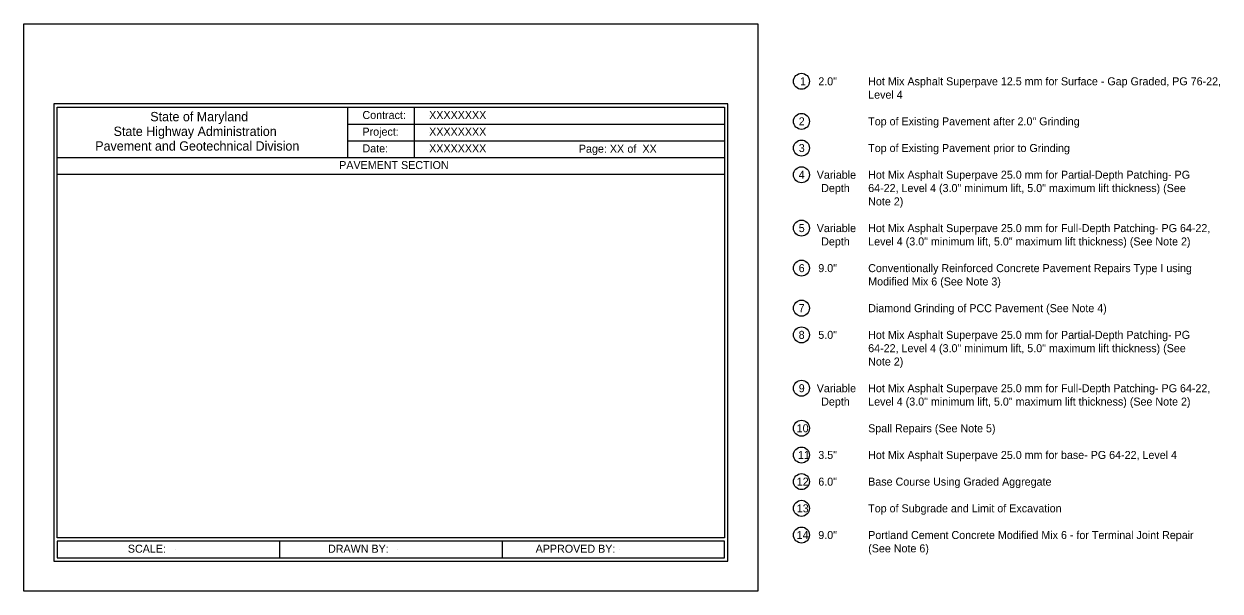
# Model space of a CAD drawing. Extents: x 0 to 17.9, y 0 to 8.5.
import ezdxf

# ---------------------------------------------------------------- set-up
doc = ezdxf.new("R2010")
doc.units = 0
for name, color, linetype in [('BORD-LINE', 7, 'Continuous'), ('BORD-TEXT', 7, 'Continuous'), ('DETL-LABL', 7, 'Continuous'), ('TTLB-TEXT', 7, 'Continuous'), ('USER-PAGE', 7, 'Continuous')]:
    doc.layers.add(name, color=color, linetype=linetype)

msp = doc.modelspace()

# ---------------------------------------------------------------- linework, layer by layer
at = {"layer": 'BORD-LINE'}
for p, q in [((4.85, 7.25), (4.85, 6.5)), ((5.85, 7.25), (5.85, 6.5)), ((4.85, 7), (10.5, 7)), ((6.075, 7.125), (6.075, 7.125)), ((6.075, 6.875), (6.075, 6.875)), ((4.85, 6.75), (10.5, 6.75)), ((0.5, 6.5), (10.5, 6.5)), ((6.075, 6.625), (6.075, 6.625)), ((8.883, 6.62), (8.883, 6.62)), ((9.372, 6.62), (9.372, 6.62)), ((0.5, 6.25), (10.5, 6.25)), ((3.833, 0.75), (3.833, 0.5)), ((7.167, 0.75), (7.167, 0.5)), ((2.267, 0.625), (2.267, 0.625)), ((5.6, 0.625), (5.6, 0.625)), ((8.933, 0.625), (8.933, 0.625)), ((0.5, 0.5), (10.5, 0.5))]:
    msp.add_line(p, q, dxfattribs=at)
for points in [[(0.45, 7.3), (0.45, 0.45), (10.55, 0.45), (10.55, 7.3)], [(0.5, 0.8), (0.5, 7.25), (10.5, 7.25), (10.5, 0.8)], [(0.5, 0.5), (10.5, 0.5), (10.5, 0.75), (0.5, 0.75)]]:
    msp.add_lwpolyline(points, close=True, dxfattribs=at)
at = {"layer": 'DETL-LABL'}
for centre in [(11.656, 7.64), (11.656, 7.04), (11.656, 6.64), (11.656, 6.24), (11.656, 5.44), (11.656, 4.84), (11.656, 4.24), (11.656, 3.84), (11.656, 3.04), (11.656, 2.44), (11.656, 2.039), (11.656, 1.64), (11.656, 1.24), (11.656, 0.84)]:
    msp.add_circle(centre, 0.12, dxfattribs=at)
at = {"layer": 'USER-PAGE'}
msp.add_lwpolyline([(11, 8.5), (11, 0), (0, 0), (0, 8.5)], close=True, dxfattribs=at)

# ---------------------------------------------------------------- texts
at = {"layer": 'BORD-TEXT'}
for s, height, p in [('State of Maryland', 0.14, (1.894, 7.041)), ('Contract:', 0.12, (5.075, 7.075)), ('State Highway Administration', 0.14, (1.344, 6.821)), ('Project:', 0.12, (5.075, 6.825)), ('Pavement and Geotechnical Division', 0.14, (1.069, 6.601)), ('Date:', 0.12, (5.075, 6.575)), ('Page:', 0.12, (8.319, 6.57)), ('of', 0.12, (9.046, 6.57)), ('PAVEMENT SECTION', 0.12, (4.726, 6.325)), ('SCALE:', 0.12, (1.558, 0.575)), ('DRAWN BY:', 0.12, (4.559, 0.575)), ('APPROVED BY:', 0.12, (7.671, 0.575))]:
    msp.add_text(s, height=height, dxfattribs=at).set_placement(p)
at = {"layer": 'DETL-LABL'}
for s, p in [('1', (11.634, 7.58)), ('2.0"', (11.908, 7.58)), ('Hot Mix Asphalt Superpave 12.5 mm for Surface - Gap Graded, PG 76-22, ', (12.656, 7.58)), ('Level 4', (12.656, 7.38)), ('2', (11.615, 6.98)), ('Top of Existing Pavement after 2.0" Grinding', (12.656, 6.98)), ('3', (11.615, 6.58)), ('Top of Existing Pavement prior to Grinding', (12.656, 6.58)), ('4', (11.614, 6.18)), ('Variable', (11.885, 6.18)), ('Hot Mix Asphalt Superpave 25.0 mm for Partial-Depth Patching- PG ', (12.656, 6.18)), ('Depth', (11.951, 5.98)), ('64-22, Level 4 (3.0" minimum lift, 5.0" maximum lift thickness) (See ', (12.656, 5.98)), ('Note 2)', (12.656, 5.78)), ('5', (11.615, 5.38)), ('Variable', (11.885, 5.38)), ('Hot Mix Asphalt Superpave 25.0 mm for Full-Depth Patching- PG 64-22, ', (12.656, 5.38)), ('Depth', (11.951, 5.18)), ('Level 4 (3.0" minimum lift, 5.0" maximum lift thickness) (See Note 2)', (12.656, 5.18)), ('6', (11.614, 4.78)), ('9.0"', (11.908, 4.78)), ('Conventionally Reinforced Concrete Pavement Repairs Type I using ', (12.656, 4.78)), ('Modified Mix 6 (See Note 3)', (12.656, 4.58)), ('Diamond Grinding of PCC Pavement (See Note 4)', (12.656, 4.18)), ('7', (11.613, 4.18)), ('8', (11.614, 3.78)), ('5.0"', (11.908, 3.78)), ('Hot Mix Asphalt Superpave 25.0 mm for Partial-Depth Patching- PG ', (12.656, 3.78)), ('64-22, Level 4 (3.0" minimum lift, 5.0" maximum lift thickness) (See ', (12.656, 3.58)), ('Note 2)', (12.656, 3.38)), ('9', (11.615, 2.98)), ('Variable', (11.885, 2.98)), ('Hot Mix Asphalt Superpave 25.0 mm for Full-Depth Patching- PG 64-22, ', (12.656, 2.98)), ('Depth', (11.951, 2.78)), ('Level 4 (3.0" minimum lift, 5.0" maximum lift thickness) (See Note 2)', (12.656, 2.78)), ('10', (11.584, 2.38)), ('Spall Repairs (See Note 5)', (12.656, 2.38)), ('11', (11.604, 1.98)), ('3.5"', (11.908, 1.98)), ('Hot Mix Asphalt Superpave 25.0 mm for base- PG 64-22, Level 4', (12.656, 1.98)), ('12', (11.585, 1.58)), ('6.0"', (11.908, 1.58)), ('Base Course Using Graded Aggregate', (12.656, 1.58)), ('13', (11.585, 1.18)), ('Top of Subgrade and Limit of Excavation', (12.656, 1.18)), ('14', (11.584, 0.78)), ('9.0"', (11.908, 0.78)), ('Portland Cement Concrete Modified Mix 6 - for Terminal Joint Repair ', (12.656, 0.78)), ('(See Note 6)', (12.656, 0.58))]:
    msp.add_text(s, height=0.12, dxfattribs=at).set_placement(p)
at = {"layer": 'TTLB-TEXT'}
for s, p in [('XXXXXXXX', (6.075, 7.075)), ('XXXXXXXX', (6.075, 6.825)), ('XXXXXXXX', (6.075, 6.575)), ('XX', (8.783, 6.57)), ('XX', (9.272, 6.57))]:
    msp.add_text(s, height=0.12, dxfattribs=at).set_placement(p)

doc.saveas('drawing.dxf')
